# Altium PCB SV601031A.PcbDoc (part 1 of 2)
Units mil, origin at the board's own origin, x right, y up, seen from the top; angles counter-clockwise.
Board outline 4000 x 2000 mil, 6 copper layers (Top Layer, MidLayer1, MidLayer2, Mid-Layer 3, Mid-Layer 4, Bottom Layer), stack 60.8 mil thick; 81 components, 26 nets, 217 pads, 227 vias.
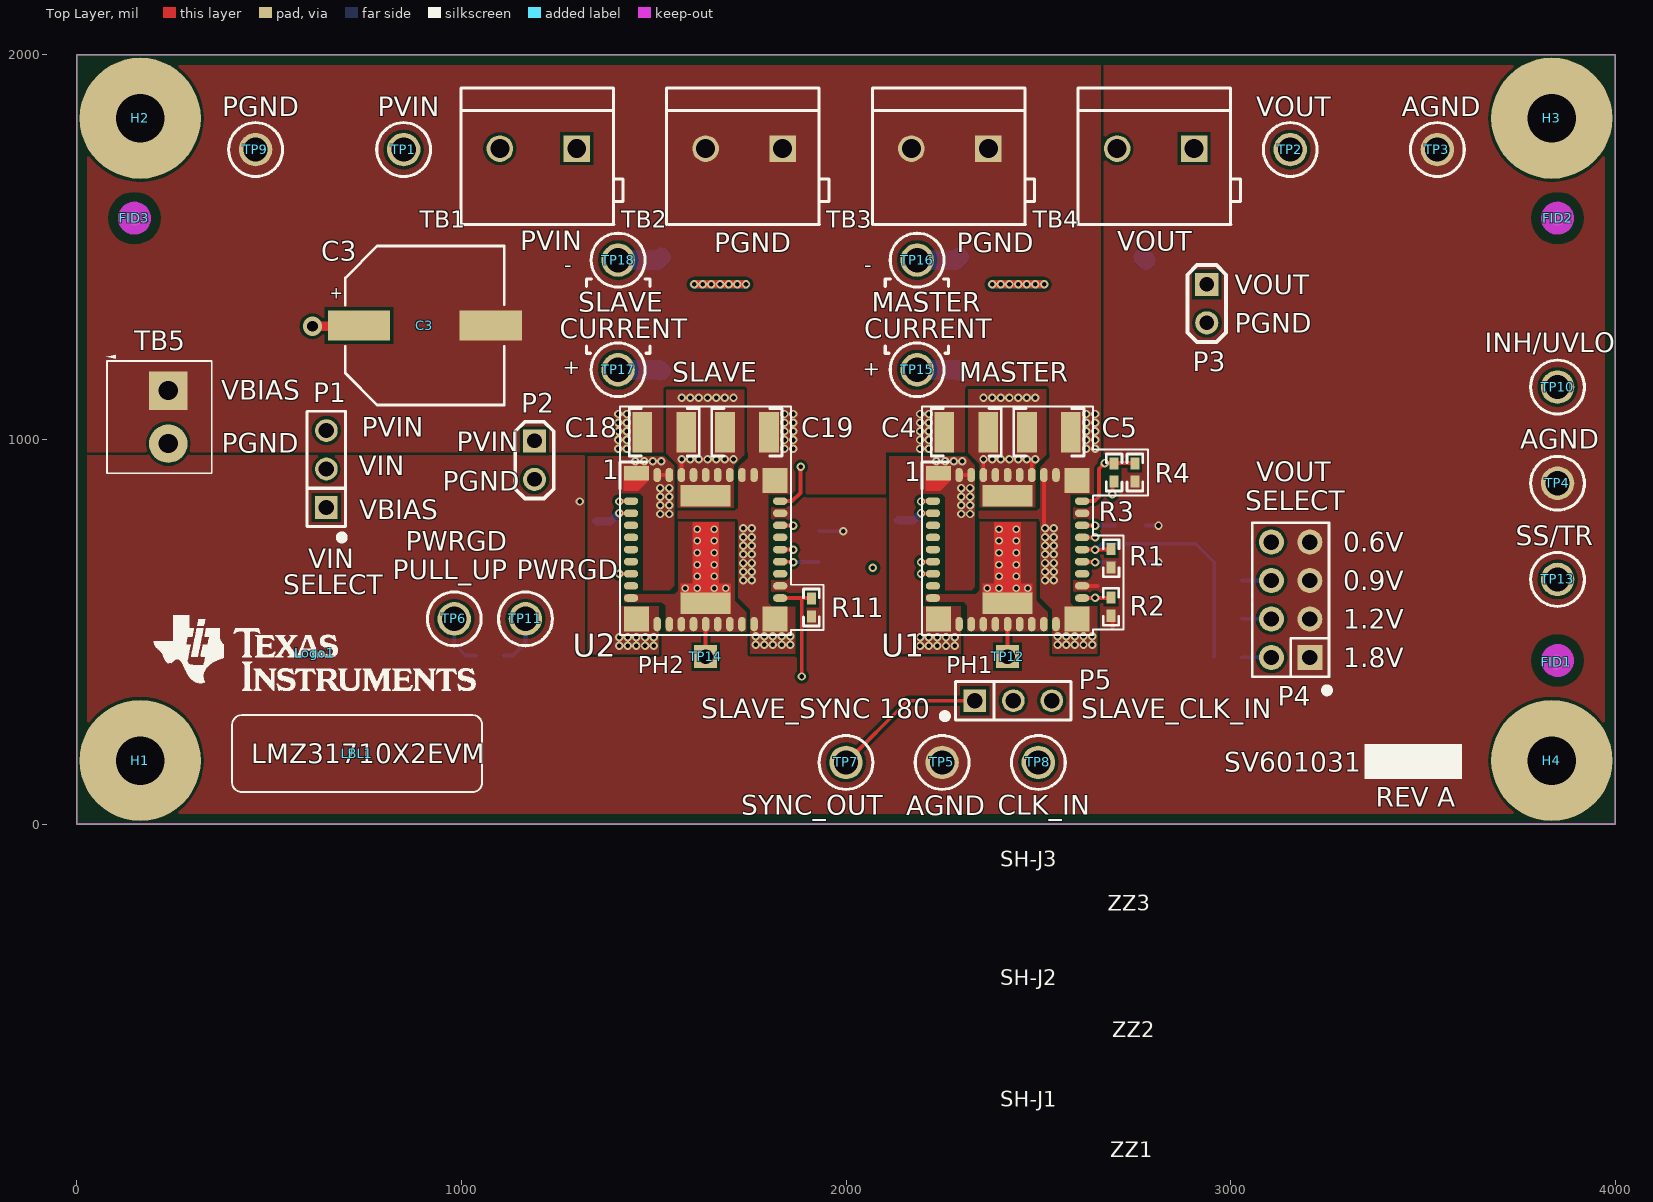
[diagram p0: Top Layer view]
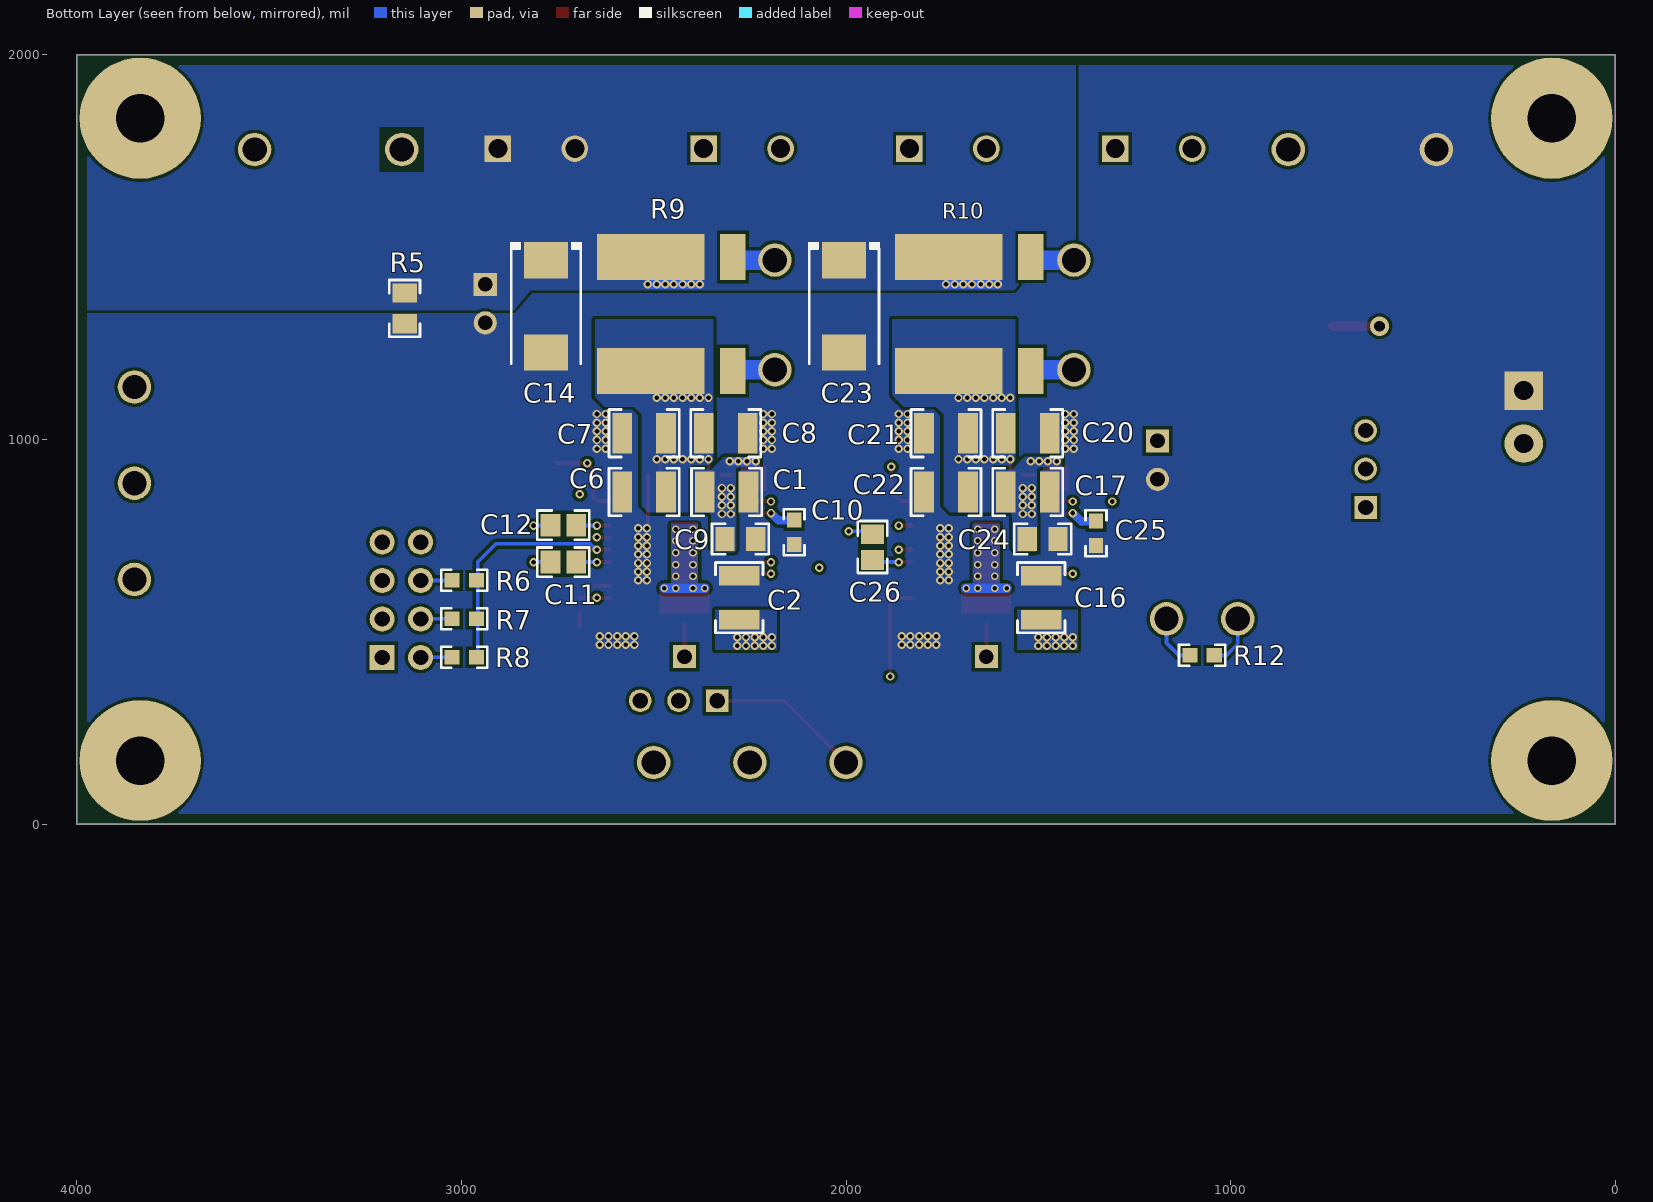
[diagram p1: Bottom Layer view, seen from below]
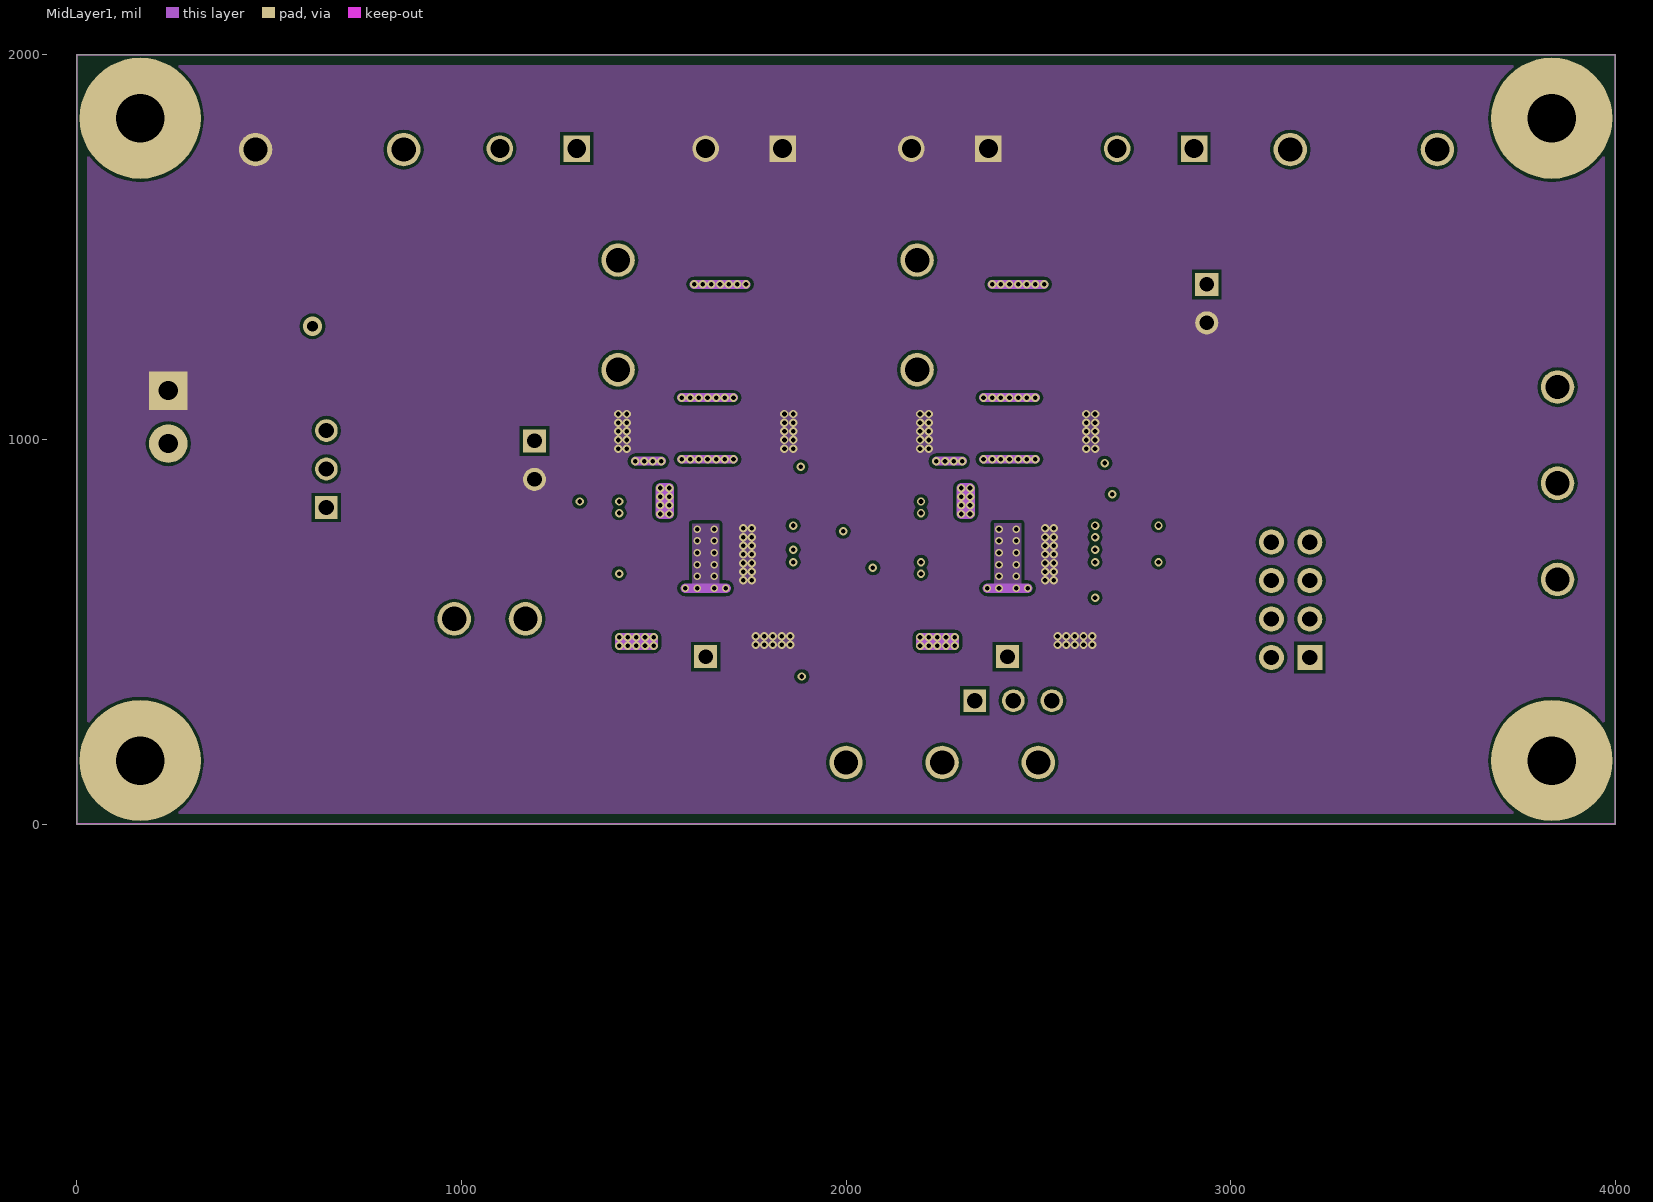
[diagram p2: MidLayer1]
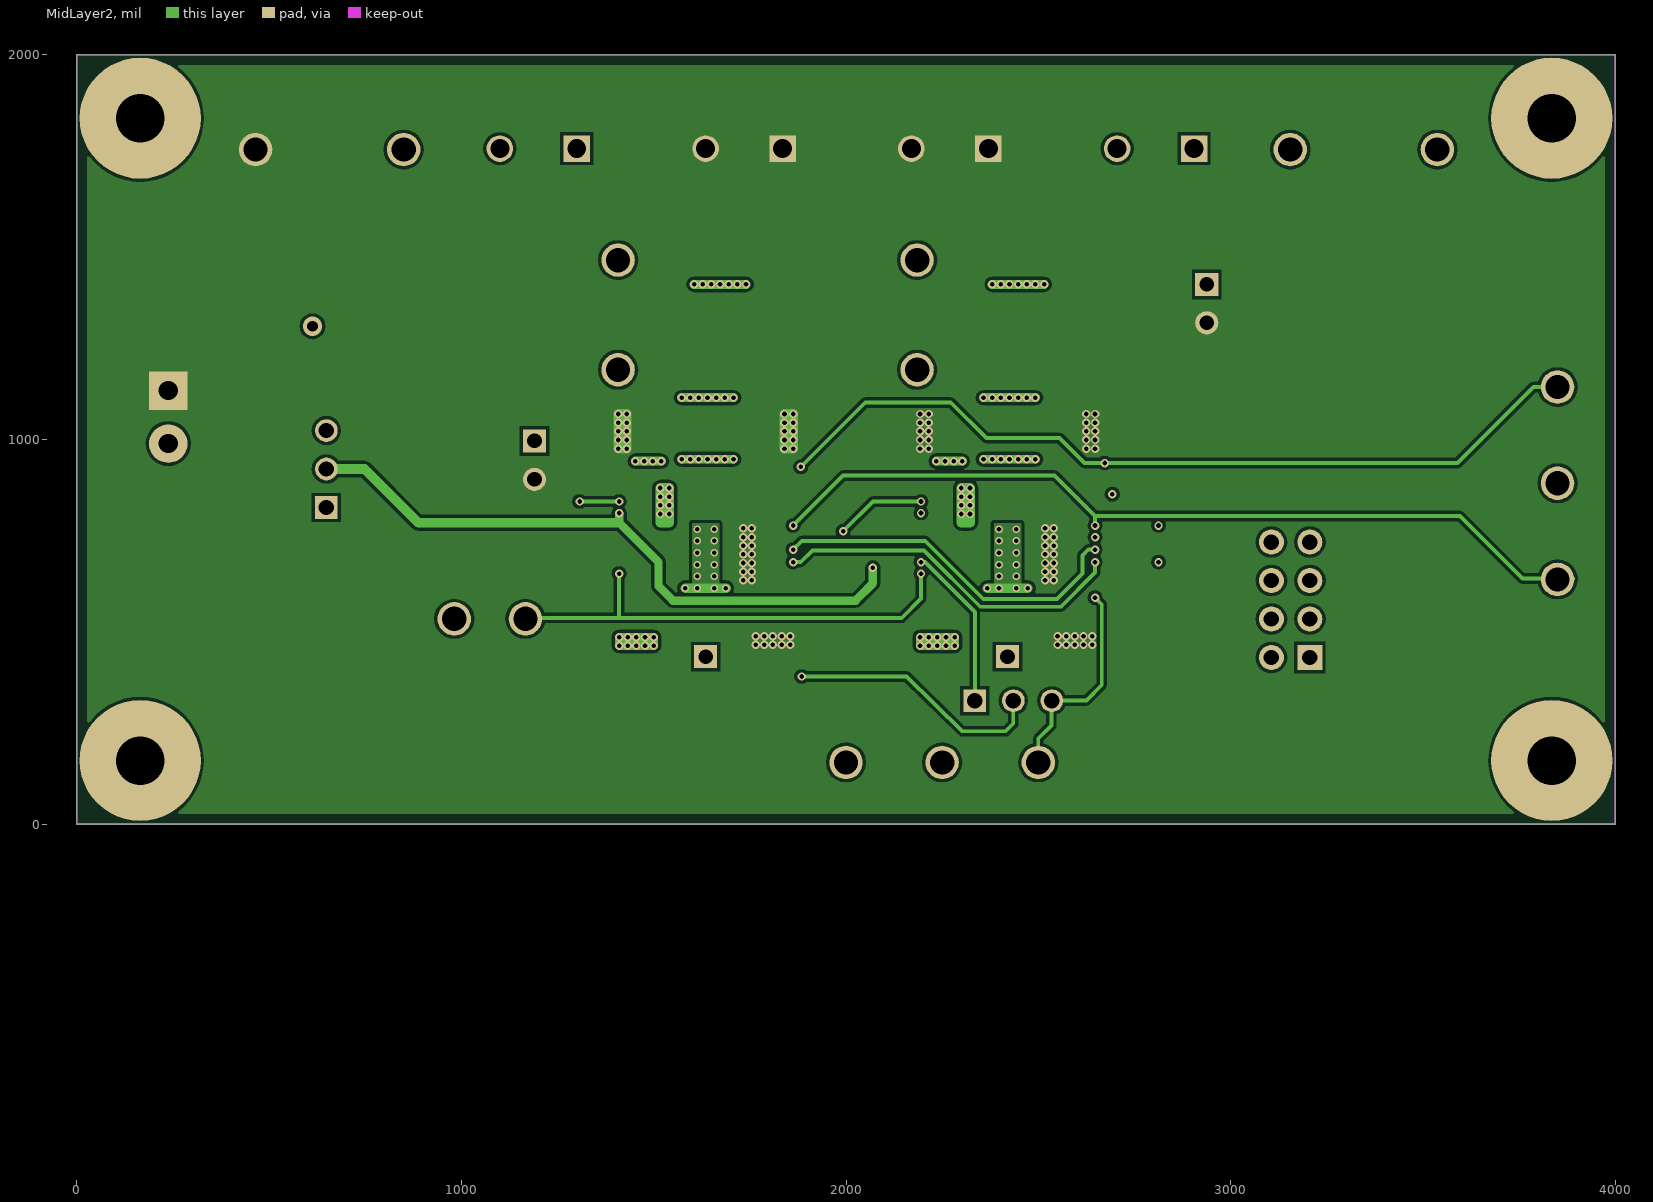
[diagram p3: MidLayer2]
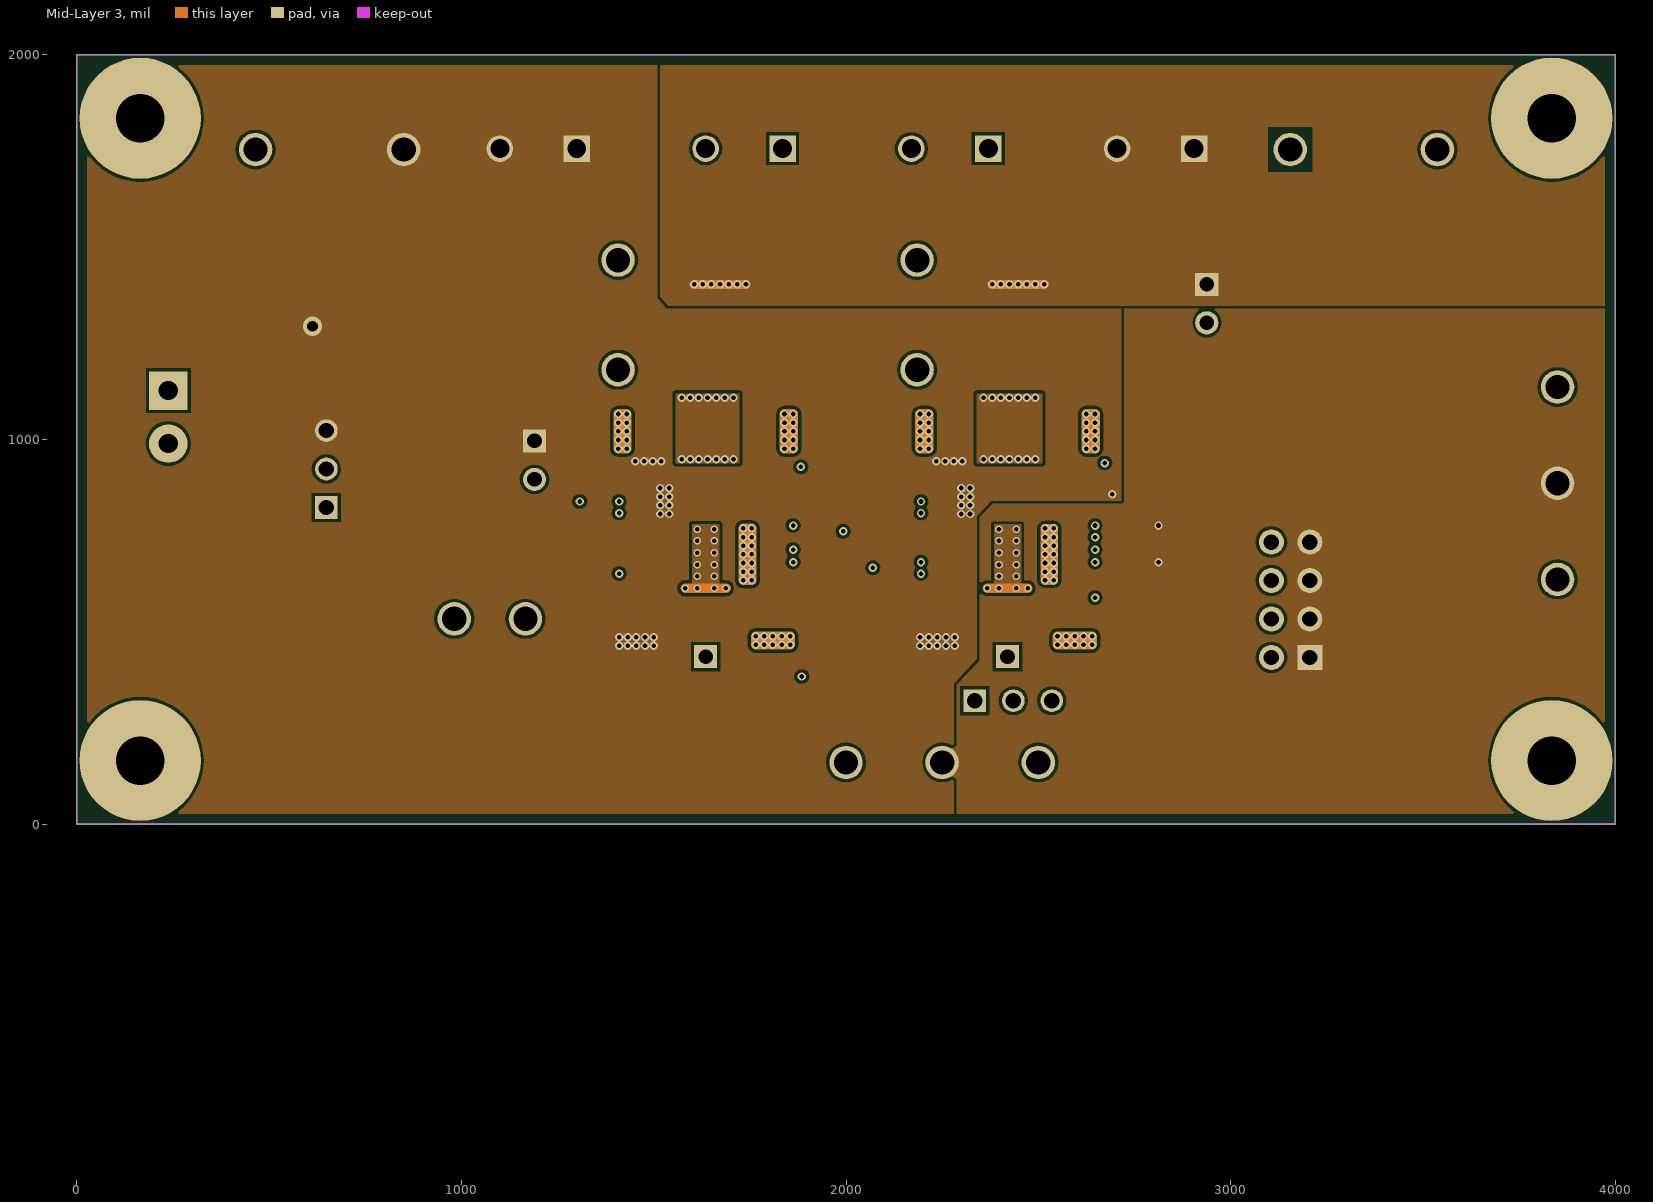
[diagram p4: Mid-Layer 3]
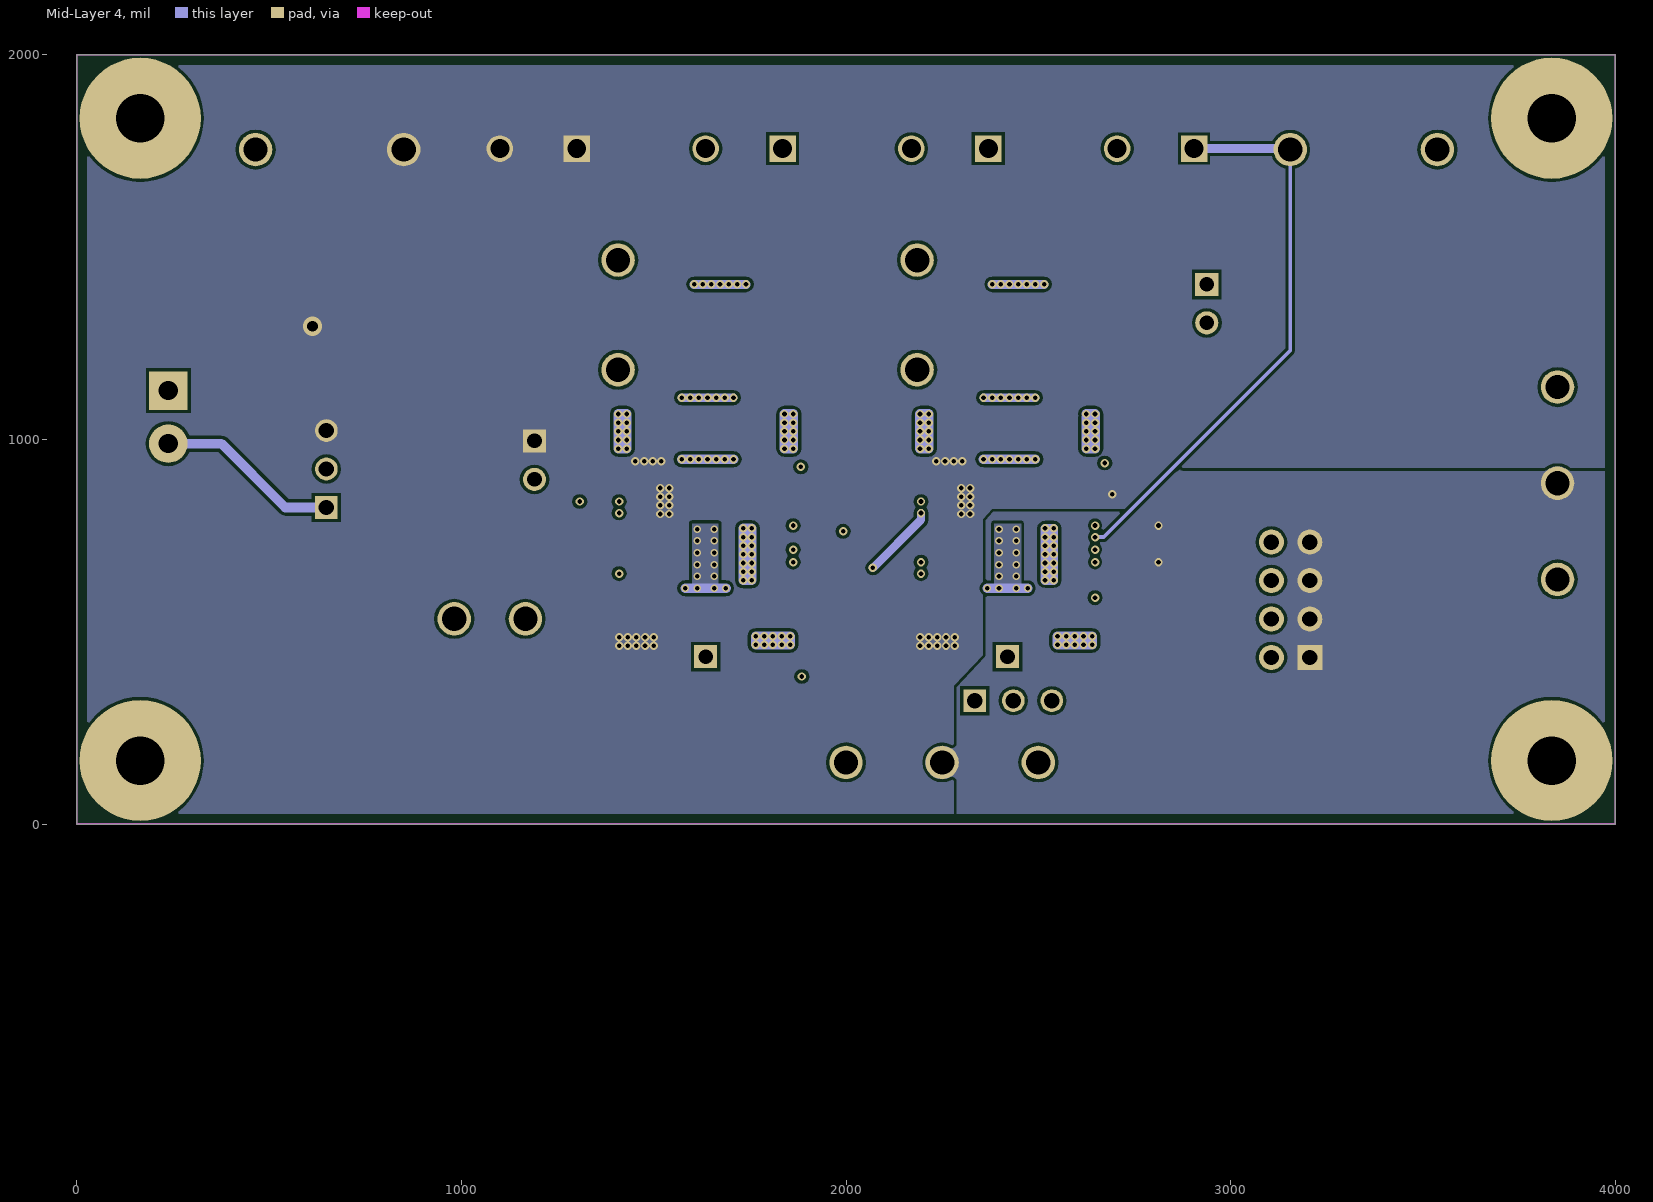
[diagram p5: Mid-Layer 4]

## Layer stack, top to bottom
Top Layer: signal copper 2.8
Dielectric: core 6, FR-4, Dk 4.8
MidLayer1: signal copper 2.8
Dielectric: prepreg 13, FR-4, Dk 4.8
MidLayer2: signal copper 2.8
Dielectric: core 6, FR-4, Dk 4.8
Mid-Layer 3: signal copper 2.8
Dielectric: prepreg 13, FR-4, Dk 4.8
Mid-Layer 4: signal copper 2.8
Dielectric: core 6, FR-4, Dk 4.8
Bottom Layer: signal copper 2.8

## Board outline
0,0 0,2000 4000,2000 4000,0

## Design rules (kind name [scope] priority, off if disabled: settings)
AcuteAngle [All] p1: minimum=4.50000000000000E+0001 checktracksonly=FALSE
AssemblyTestPointUsage [All] p1: valid=2
AssemblyTestpoint [All] p1: testpointundercomponent=TRUE minsize=20 maxsize=100 preferedsize=60 minholesize=0 maxholesize=40 preferedholesize=32 testpointgrid=1 usegrid=FALSE gridtolerance=0.01 allowsidetop=TRUE allowsidebottom=TRUE
Clearance Clearance_1 [IsVia vs IsVia] p1 off: gap=0
Clearance Clearance_BoardEdge_MountingHoles [OnCopper and InComponentClass('Mounting Holes') vs IsKeepOut] p2: gap=4
Clearance Clearance_BoardEdge_Poly [OnCopper and InPoly vs IsKeepOut] p3: gap=25
Clearance Clearance_BoardEdge [OnCopper and Not InComponentClass('Logo') and not InComponentClass('FiducialMark') and not InRegion(1000,500,4000,800) and Not IsKeepout vs IsKeepOut] p4: gap=75
Clearance Clearance_Poly [InPolygon] p5: gap=8
Clearance [All] p6: gap=8
ComponentClearance ComponentClearance_1 [InComponent('U2') vs InComponent('TP14')] p1: gap=5 collisioncheckmode=3 verticalgap=5 showdistances=FALSE
ComponentClearance ComponentClearance_U1-TP12 [InComponent('U1') vs InComponent('TP12')] p2: gap=5 collisioncheckmode=3 verticalgap=5 showdistances=FALSE
ComponentClearance ComponentClearance_Logo-TP6 [InComponent('Logo1') vs InComponent('TP6')] p3: gap=0 collisioncheckmode=3 verticalgap=0 showdistances=FALSE
ComponentClearance ComponentClearance_P5-TP12 [InComponent('P5') vs InComponent('TP12')] p4: gap=8 collisioncheckmode=3 verticalgap=20 showdistances=FALSE
ComponentClearance ComponentClearance_Logo [InComponentClass('Logo')] p5: gap=50 collisioncheckmode=3 verticalgap=10 showdistances=FALSE
ComponentClearance ComponentClearance_ScrewToNut [(HasFootprint('NY PMS 440 0025 PH')) vs (HasFootprint('Keystone_1902C'))] p6: gap=5 collisioncheckmode=3 verticalgap=10 showdistances=FALSE
ComponentClearance ComponentClearance_MountingHoles [InComponentClass('Mounting Holes')] p7: gap=50 collisioncheckmode=3 verticalgap=50 showdistances=FALSE
ComponentClearance ComponentClearance_SmallPassives [HasFootprint('0201*') or HasFootprint('0402*') or HasFootprint('0508') or HasFootprint('0603*') or HasFootprint('0612') or HasFootprint('0805*') or HasFootprint('0815*') or HasFootprint('0830*') or HasFootprint('1206*') or HasFootprint('1210*') or HasFootprint('1808*') or HasFootprint('1812*') or HasFootprint('1825*') or HasFootprint('2010*') or HasFootprint('2220*') or HasFootprint('2225*') or HasFootprint('2512*') or HasFootprint('2728*') or HasFootprint('3518*') vs HasFootprint('0201*') or HasFootprint('0402*') or HasFootprint('0508') or HasFootprint('0603*') or HasFootprint('0612') or HasFootprint('0805*') or HasFootprint('0815*') or HasFootprint('0830*') or HasFootprint('1206*') or HasFootprint('1210*') or HasFootprint('1808*') or HasFootprint('1812*') or HasFootprint('1825*') or HasFootprint('2010*') or HasFootprint('2220*') or HasFootprint('2225*') or HasFootprint('2512*') or HasFootprint('2728*') or HasFootprint('3518*')] p8: gap=20 collisioncheckmode=3 verticalgap=10 showdistances=FALSE
ComponentClearance ComponentClearance_THtoSMT [IsThruComponent vs IsSMTComponent] p9: gap=30 collisioncheckmode=3 verticalgap=30 showdistances=FALSE
ComponentClearance ComponentClearance_THtoTH_2 [IsThruComponent vs IsThruComponent] p10: gap=30 collisioncheckmode=3 verticalgap=20 showdistances=FALSE
ComponentClearance [All] p11: gap=15 collisioncheckmode=3 verticalgap=10 showdistances=FALSE
DiffPairsRouting [All] p1: maxlimit=100 minlimit=10 mostfreqgap=10 maxuncoupledlength=1000
FabricationTestPointUsage TestPointUsage [All] p1: valid=2 allowmultiple=FALSE
FabricationTestpoint Testpoint [All] p1: side=3 testpointundercomponent=TRUE minsize=20 maxsize=100 preferedsize=60 minholesize=0 maxholesize=40 preferedholesize=32 testpointgrid=1 allowsidetop=TRUE allowsidebottom=TRUE usegrid=FALSE gridtolerance=0.01
FanoutControl Fanout_LCC [IsLCC] p1: bgadir=Out bgaviamode=Centered fanoutstyle=Auto fanoutdirection=Alternating viagrid=1 // Fanout_LCC (Default Rule)
FanoutControl Fanout_BGA [IsBGA] p2: bgadir=Out bgaviamode=Centered fanoutstyle=Auto fanoutdirection=Alternating viagrid=1 // Fanout_BGA (Default Rule)
FanoutControl Fanout_Default [All] p4: bgadir=Out bgaviamode=Centered fanoutstyle=Auto fanoutdirection=Alternating viagrid=1 // Fanout_Default (Default Rule)
FanoutControl Fanout_Small [(CompPinCount < 5)] p5: bgadir=Out bgaviamode=Centered fanoutstyle=Auto fanoutdirection=OutThenIn viagrid=1 // Fanout_Small (Default Rule)
HoleSize [All] p1: absolutevalues=TRUE maxlimit=251 minlimit=8 maxpercent=80.000 minpercent=20.000
MinimumAnnularRing MinimumAnnularRing_2 [InNet('PH')] p1: minimumring=3
MinimumAnnularRing MinimumAnnularRing_1 [InNet('PH2')] p2: minimumring=3
MinimumAnnularRing [All] p3: minimumring=5
MinimumSolderMaskSliver MinimumSolderMaskSliver_6 [InComponent('U2') vs InNet('PRE_VOUT2')] p1: minsoldermaskwidth=1
MinimumSolderMaskSliver MinimumSolderMaskSliver_5 [InComponent('U1') vs InNet('PRE_VOUT')] p2: minsoldermaskwidth=1
MinimumSolderMaskSliver MinimumSolderMaskSliver_4 [InComponent('C24') vs IsVia] p3: minsoldermaskwidth=1
MinimumSolderMaskSliver MinimumSolderMaskSliver_3 [InComponent('R10') vs IsVia] p4: minsoldermaskwidth=1
MinimumSolderMaskSliver MinimumSolderMaskSliver_1 [InComponent('R9') vs IsVia] p5: minsoldermaskwidth=1
MinimumSolderMaskSliver MinimumSolderMaskSliver_2 [InComponent('C9') vs IsVia] p6: minsoldermaskwidth=1
MinimumSolderMaskSliver [All] p7: minsoldermaskwidth=4
MinimumSolderMaskSliver MinimumSolderMaskSliver_Logo [InComponentClass('Logo') vs InComponentClass('Logo')] p8: minsoldermaskwidth=0.7
PlaneClearance [All] p1: clearance=8
PlaneConnect [All] p1: planeconnectstyle=Relief reliefexpansion=10 reliefentries=4 reliefconductorwidth=10 reliefairgap=10
PolygonConnect PolygonConnect_53 [All vs IsNamedPolygon('Bottom-PGND')] p1: connectstyle=Direct reliefconductorwidth=10 reliefentries=4 polygonreliefangle="90 Angle" airgapwidth=10
PolygonConnect PolygonConnect_52 [All vs IsNamedPolygon('Bottom-VOUT')] p2: connectstyle=Direct reliefconductorwidth=10 reliefentries=4 polygonreliefangle="90 Angle" airgapwidth=10
PolygonConnect PolygonConnect_51 [All vs IsNamedPolygon('Bottom-PH')] p3: connectstyle=Direct reliefconductorwidth=10 reliefentries=4 polygonreliefangle="90 Angle" airgapwidth=10
PolygonConnect PolygonConnect_50 [All vs IsNamedPolygon('Bottom-VOUT')] p4: connectstyle=Direct reliefconductorwidth=10 reliefentries=4 polygonreliefangle="90 Angle" airgapwidth=10
PolygonConnect PolygonConnect_49 [All vs IsNamedPolygon('Bottom-PGND')] p5: connectstyle=Direct reliefconductorwidth=10 reliefentries=4 polygonreliefangle="90 Angle" airgapwidth=10
PolygonConnect PolygonConnect_48 [All vs IsNamedPolygon('Bottom-PVIN 1')] p6: connectstyle=Direct reliefconductorwidth=10 reliefentries=4 polygonreliefangle="90 Angle" airgapwidth=10
PolygonConnect PolygonConnect_47 [All vs IsNamedPolygon('Bottom-$$$2')] p7: connectstyle=Direct reliefconductorwidth=10 reliefentries=4 polygonreliefangle="90 Angle" airgapwidth=10
PolygonConnect PolygonConnect_46 [All vs IsNamedPolygon('Bottom-PVIN 3')] p8: connectstyle=Direct reliefconductorwidth=10 reliefentries=4 polygonreliefangle="90 Angle" airgapwidth=10
PolygonConnect PolygonConnect_45 [All vs IsNamedPolygon('Bottom-PVIN 2')] p9: connectstyle=Direct reliefconductorwidth=10 reliefentries=4 polygonreliefangle="90 Angle" airgapwidth=10
PolygonConnect PolygonConnect_44 [All vs IsNamedPolygon('Bottom-PH2')] p10: connectstyle=Direct reliefconductorwidth=10 reliefentries=4 polygonreliefangle="90 Angle" airgapwidth=10
PolygonConnect PolygonConnect_43 [All vs IsNamedPolygon('Bottom-$$$1')] p11: connectstyle=Direct reliefconductorwidth=10 reliefentries=4 polygonreliefangle="90 Angle" airgapwidth=10
PolygonConnect PolygonConnect_42 [All vs IsNamedPolygon('Bottom-PVIN')] p12: connectstyle=Direct reliefconductorwidth=10 reliefentries=4 polygonreliefangle="90 Angle" airgapwidth=10
PolygonConnect PolygonConnect_41 [All vs IsNamedPolygon('Bottom-$$$11361')] p13: connectstyle=Direct reliefconductorwidth=10 reliefentries=4 polygonreliefangle="90 Angle" airgapwidth=10
PolygonConnect PolygonConnect_40 [All vs IsNamedPolygon('Bottom-PGND')] p14: connectstyle=Direct reliefconductorwidth=10 reliefentries=4 polygonreliefangle="90 Angle" airgapwidth=10
PolygonConnect PolygonConnect_39 [All vs IsNamedPolygon('Bottom-VOUT')] p15: connectstyle=Direct reliefconductorwidth=10 reliefentries=4 polygonreliefangle="90 Angle" airgapwidth=10
PolygonConnect PolygonConnect_38 [All vs IsNamedPolygon('Layer 5-AGND')] p16: connectstyle=Direct reliefconductorwidth=10 reliefentries=4 polygonreliefangle="90 Angle" airgapwidth=10
PolygonConnect PolygonConnect_37 [All vs IsNamedPolygon('Layer 5-PVIN')] p17: connectstyle=Direct reliefconductorwidth=10 reliefentries=4 polygonreliefangle="90 Angle" airgapwidth=10
PolygonConnect PolygonConnect_36 [All vs IsNamedPolygon('Layer 5-PH2')] p18: connectstyle=Direct reliefconductorwidth=10 reliefentries=4 polygonreliefangle="90 Angle" airgapwidth=10
PolygonConnect PolygonConnect_35 [All vs IsNamedPolygon('Layer 5-PH')] p19: connectstyle=Direct reliefconductorwidth=10 reliefentries=4 polygonreliefangle="90 Angle" airgapwidth=10
PolygonConnect PolygonConnect_34 [All vs IsNamedPolygon('Layer 4-AGND')] p20: connectstyle=Direct reliefconductorwidth=10 reliefentries=4 polygonreliefangle="90 Angle" airgapwidth=10
PolygonConnect PolygonConnect_33 [All vs IsNamedPolygon('Layer 4-$$$')] p21: connectstyle=Direct reliefconductorwidth=10 reliefentries=4 polygonreliefangle="90 Angle" airgapwidth=10
PolygonConnect PolygonConnect_32 [All vs IsNamedPolygon('Layer 4-$$$2')] p22: connectstyle=Direct reliefconductorwidth=10 reliefentries=4 polygonreliefangle="90 Angle" airgapwidth=10
PolygonConnect PolygonConnect_31 [All vs IsNamedPolygon('Layer 4-PVIN')] p23: connectstyle=Direct reliefconductorwidth=10 reliefentries=4 polygonreliefangle="90 Angle" airgapwidth=10
PolygonConnect PolygonConnect_30 [All vs IsNamedPolygon('Layer 4-VOUT')] p24: connectstyle=Direct reliefconductorwidth=10 reliefentries=4 polygonreliefangle="90 Angle" airgapwidth=10
PolygonConnect PolygonConnect_29 [All vs IsNamedPolygon('Layer 4-PH')] p25: connectstyle=Direct reliefconductorwidth=10 reliefentries=4 polygonreliefangle="90 Angle" airgapwidth=10
PolygonConnect PolygonConnect_28 [All vs IsNamedPolygon('Layer 4-PH2')] p26: connectstyle=Direct reliefconductorwidth=10 reliefentries=4 polygonreliefangle="90 Angle" airgapwidth=10
PolygonConnect PolygonConnect_27 [All vs IsNamedPolygon('Layer 3-PGND')] p27: connectstyle=Direct reliefconductorwidth=10 reliefentries=4 polygonreliefangle="90 Angle" airgapwidth=10
PolygonConnect PolygonConnect_26 [All vs IsNamedPolygon('Layer 3-PH2')] p28: connectstyle=Direct reliefconductorwidth=10 reliefentries=4 polygonreliefangle="90 Angle" airgapwidth=10
PolygonConnect PolygonConnect_25 [All vs IsNamedPolygon('Layer 3-PH')] p29: connectstyle=Direct reliefconductorwidth=10 reliefentries=4 polygonreliefangle="90 Angle" airgapwidth=10
PolygonConnect PolygonConnect_24 [All vs IsNamedPolygon('Layer 2-PGND')] p30: connectstyle=Direct reliefconductorwidth=10 reliefentries=4 polygonreliefangle="90 Angle" airgapwidth=10
PolygonConnect PolygonConnect_23 [InNet('PGND') vs IsNamedPolygon('Layer 2-PH')] p31: connectstyle=Direct reliefconductorwidth=10 reliefentries=4 polygonreliefangle="90 Angle" airgapwidth=10
PolygonConnect PolygonConnect_22 [All vs IsNamedPolygon('Layer 2-PH2')] p32: connectstyle=Direct reliefconductorwidth=10 reliefentries=2 polygonreliefangle="90 Angle" airgapwidth=10
PolygonConnect PolygonConnect_21 [All vs IsNamedPolygon('Layer 2-PH')] p33: connectstyle=Direct reliefconductorwidth=10 reliefentries=2 polygonreliefangle="90 Angle" airgapwidth=10
PolygonConnect PolygonConnect_20 [All vs IsNamedPolygon('Layer 2-PH2')] p34: connectstyle=Direct reliefconductorwidth=10 reliefentries=4 polygonreliefangle="90 Angle" airgapwidth=10
PolygonConnect PolygonConnect_19 [All vs IsNamedPolygon('Layer 2-PH')] p35: connectstyle=Direct reliefconductorwidth=10 reliefentries=4 polygonreliefangle="90 Angle" airgapwidth=10
PolygonConnect PolygonConnect_18 [All vs IsNamedPolygon('Layer 2-PH2')] p36: connectstyle=Direct reliefconductorwidth=10 reliefentries=4 polygonreliefangle="90 Angle" airgapwidth=10
PolygonConnect PolygonConnect_17 [All vs IsNamedPolygon('Layer 2-PH')] p37: connectstyle=Direct reliefconductorwidth=10 reliefentries=4 polygonreliefangle="90 Angle" airgapwidth=10
PolygonConnect PolygonConnect_16 [All vs IsNamedPolygon('Layer 2-PH')] p38: connectstyle=Direct reliefconductorwidth=10 reliefentries=4 polygonreliefangle="90 Angle" airgapwidth=10
PolygonConnect PolygonConnect_15 [All vs IsNamedPolygon('Top-$$$')] p39: connectstyle=Direct reliefconductorwidth=10 reliefentries=4 polygonreliefangle="90 Angle" airgapwidth=10
PolygonConnect PolygonConnect_14 [All vs IsNamedPolygon('Top-AGND')] p40: connectstyle=Direct reliefconductorwidth=10 reliefentries=4 polygonreliefangle="90 Angle" airgapwidth=10
PolygonConnect PolygonConnect_13 [All vs IsNamedPolygon('Top-PGND 1')] p41: connectstyle=Direct reliefconductorwidth=10 reliefentries=4 polygonreliefangle="90 Angle" airgapwidth=10
PolygonConnect PolygonConnect_12 [All vs IsNamedPolygon('Top-$$$')] p42: connectstyle=Direct reliefconductorwidth=10 reliefentries=4 polygonreliefangle="90 Angle" airgapwidth=10
PolygonConnect PolygonConnect_11 [All vs IsNamedPolygon('Top-$$$')] p43: connectstyle=Direct reliefconductorwidth=10 reliefentries=4 polygonreliefangle="90 Angle" airgapwidth=10
PolygonConnect PolygonConnect_10 [All vs IsNamedPolygon('Top-$$$2')] p44: connectstyle=Direct reliefconductorwidth=10 reliefentries=4 polygonreliefangle="90 Angle" airgapwidth=10
PolygonConnect PolygonConnect_9 [All vs IsNamedPolygon('Top-PGND 2')] p45: connectstyle=Direct reliefconductorwidth=10 reliefentries=4 polygonreliefangle="90 Angle" airgapwidth=10
PolygonConnect PolygonConnect_8 [All vs IsNamedPolygon('Top-PVIN 2')] p46: connectstyle=Direct reliefconductorwidth=10 reliefentries=4 polygonreliefangle="90 Angle" airgapwidth=10
PolygonConnect PolygonConnect_7 [All vs IsNamedPolygon('Top-PVIN 1')] p47: connectstyle=Direct reliefconductorwidth=10 reliefentries=4 polygonreliefangle="90 Angle" airgapwidth=10
PolygonConnect PolygonConnect_6 [All vs IsNamedPolygon('Top-PH2')] p48: connectstyle=Direct reliefconductorwidth=10 reliefentries=4 polygonreliefangle="90 Angle" airgapwidth=10
PolygonConnect PolygonConnect_5 [All vs IsNamedPolygon('Top-PVIN 1')] p49: connectstyle=Direct reliefconductorwidth=10 reliefentries=4 polygonreliefangle="90 Angle" airgapwidth=10
PolygonConnect PolygonConnect_4 [All vs IsNamedPolygon('Top-PH2')] p50: connectstyle=Direct reliefconductorwidth=10 reliefentries=4 polygonreliefangle="90 Angle" airgapwidth=10
PolygonConnect PolygonConnect_3 [All vs IsNamedPolygon('Top-PH2')] p51: connectstyle=Direct reliefconductorwidth=10 reliefentries=4 polygonreliefangle="90 Angle" airgapwidth=10
PolygonConnect PolygonConnect_2 [All vs IsNamedPolygon('Top-PGND')] p52: connectstyle=Direct reliefconductorwidth=10 reliefentries=4 polygonreliefangle="90 Angle" airgapwidth=10
PolygonConnect PolygonConnect_1 [All vs IsNamedPolygon('Top-PH')] p53: connectstyle=Direct reliefconductorwidth=10 reliefentries=4 polygonreliefangle="90 Angle" airgapwidth=10
PolygonConnect [All] p54: connectstyle=Relief reliefconductorwidth=10 reliefentries=4 polygonreliefangle="90 Angle" airgapwidth=10
RoutingVias [All] p1: holewidth=12 width=24 viastyle="Through Hole" minholewidth=8 minwidth=19 maxholewidth=40 maxwidth=65
SMDToCorner [All] p1: distance=30000
SilkToSilkClearance [All] p1: silktosilkclearance=1
SilkscreenOverComponentPads [All] p1: minsilkscreentomaskgap=5
SolderMaskExpansion [All] p1: expansion=3
Width [All] p1: maxlimit=100 minlimit=6 preferedwidth=10 checkconnectedcopper=TRUE
12 further rules are at their usual default settings.

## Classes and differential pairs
component class Shunt: SH-J1 SH-J2 SH-J3
component class "Mounting Holes": H1 H2 H3 H4
component class Label: LBL1
component class AssemblyNote: ZZ2 ZZ3
component class FiducialMark: FID1 FID2 FID3
component class Logo: Logo1

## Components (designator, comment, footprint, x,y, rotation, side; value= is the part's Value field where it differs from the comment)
C1 "12103D226MAT2A" 1210 2310.5,863.5 r180 bottom
C2 "12103D226MAT2A" 1210 2277.5,588.5 r90 bottom
C3 "EEE-FC1E221P" SM_RADIAL_G 905,1296 r0 top
C4 "GRM32EC80J107ME20L" 1210 2527.5,1018.5 r0 top
C5 "GRM32EC80J107ME20L" 1210 2312.5,1018.5 r180 top
C6 "GRM32EC80J107ME20L" 1210 2525,863.5 r0 bottom
C7 "GRM32EC80J107ME20L" 1210 2312.5,1016 r180 bottom
C8 "GRM32EC80J107ME20L" 1210 2525,1016 r0 bottom
C9 "C0805C104K3RACTU" 0805_HV 2274.5,741 r180 bottom
C10 "GRM188R60J475KE19D" 0603 2135,758.5 r270 bottom
C11 "GRM2165C2A101JA01D" 0805 2735,681 r0 bottom
C12 "C0805C332K5RACTU" 0805 2735,777 r0 bottom
C14 "10TPB220M" TPB_D4 2780,1346 r270 bottom
C16 "12103D226MAT2A" 1210 1492.5,588.5 r90 bottom
C17 "12103D226MAT2A" 1210 1527.5,863.5 r180 bottom
C18 "GRM32EC80J107ME20L" 1210 1742.5,1018.5 r0 top
C19 "GRM32EC80J107ME20L" 1210 1527.5,1018.5 r180 top
C20 "GRM32EC80J107ME20L" 1210 1740,1016 r0 bottom
C21 "GRM32EC80J107ME20L" 1210 1527.5,1016 r180 bottom
C22 "GRM32EC80J107ME20L" 1210 1740,863.5 r0 bottom
C23 "10TPB220M" TPB_D4 2005,1346 r270 bottom
C24 "C0805C104K3RACTU" 0805_HV 1488.5,741 r180 bottom
C25 "GRM188R60J475KE19D" 0603 1350,756 r270 bottom
C26 "GRM2165C2A101JA01D" 0805 1931,720 r90 bottom
FID1 "Fiducial" Fiducial10-20#1 3850,425 r0 top
FID2 "Fiducial" Fiducial10-20#2 3850,1575 r0 top
FID3 "Fiducial" Fiducial10-20#2 150,1575 r0 top
H1 "NY PMS 440 0025 PH" "NY PMS 440 0025 PH" 165,165 r90 top
H2 "NY PMS 440 0025 PH" "NY PMS 440 0025 PH" 165,1835 r90 top
H3 "NY PMS 440 0025 PH" "NY PMS 440 0025 PH" 3835,1835 r90 top
H4 "NY PMS 440 0025 PH" "NY PMS 440 0025 PH" 3835,165 r180 top
LBL1 "Size: 0.65\" x 0.20 \"" Label_650x200 729,183 r180 top
Logo1 "Texas Instruments" TI_Stacked_Overlay_Small 619,444 r0 top
P1 "PEC03SAAN" CONN_PEC03SAAN 649,923 r90 top
P2 "310-93-102-41-001000" HDR100_1X2 1190,996 r270 top
P3 "310-93-102-41-001000" HDR100_1X2 2938,1403 r270 top
P4 "PEC04DAAN" CONN_PEC04DAAN 3156,583 r90 top
P5 "PEC03SAAN" CONN_PEC03SAAN 2435,320.5 r0 top
R1 "CRCW04022K15FKED" 0402 2689.5,691 r90 top
R2 "CRCW0402487KFKED" 0402 2689,565 r90 top
R3 "CRCW040268K1FKED" 0402 2697,914 r270 top
R4 "CRCW040224K3FKED" 0402 2751,914 r90 top
R5 "ERJ-6GEYJ102V" 0805_HV 3147.5,1340.5 r270 bottom
R6 "CRCW06032K87FKEA" 0603 2992.5,633.5 r180 bottom
R7 "CRCW06031K43FKEA" 0603 2992.5,533.5 r180 bottom
R8 "CRCW0603715RFKEA" 0603 2992.5,433.5 r180 bottom
R9 "R-WSL3637" CSM-3637 2455,1326 r270 bottom
R10 "R-WSL3637" CSM-3637 1680,1326 r270 bottom
R11 "CRCW0402487KFKED" 0402 1910,563 r90 top
R12 "CRCW0603100KJNEA" 0603 1074,438.5 r180 bottom
SH-J1 "2SN-BK-G" 2SN-BK-G 2437,-844 r90 top
SH-J2 "2SN-BK-G" 2SN-BK-G 2437,-528 r90 top
SH-J3 "2SN-BK-G" 2SN-BK-G 2437,-219 r90 top
TB1 "ED120/2DS" CONN_ED120-2DS 1200,1756 r90 top
TB2 "ED120/2DS" CONN_ED120-2DS 1735,1756 r90 top
TB3 "ED120/2DS" CONN_ED120-2DS 2270,1756 r90 top
TB4 "ED120/2DS" CONN_ED120-2DS 2805,1756 r90 top
TB5 "ED555/2DS" TERM_BLK_ED555-2DS 238,1127 r270 top
TP1 "5010" Keystone5010 850,1753.5 r0 top
TP2 "5010" Keystone5010 3155,1753.5 r90 top
TP3 "5011" Keystone5011 3537.5,1753.5 r0 top
TP4 "5011" Keystone5011 3850,886 r0 top
TP5 "5011" Keystone5011 2250,160 r0 top
TP6 "5012" Keystone5012 981.5,533.5 r0 top
TP7 "5012" Keystone5012 2000,160 r0 top
TP8 "5012" Keystone5012 2500,160 r0 top
TP9 "5011" Keystone5011 465,1753.5 r180 top
TP10 "5012" Keystone5012 3850,1136 r90 top
TP11 "5012" Keystone5012 1166.5,533.5 r0 top
TP12 "Comment" TP-038 2420,435 r0 top
TP13 "5012" Keystone5012 3850,636 r90 top
TP14 "Comment" TP-038 1635,435 r0 top
TP15 "5012" Keystone5012 2185,1181 r0 top
TP16 "5012" Keystone5012 2185,1466 r0 top
TP17 "5012" Keystone5012 1407.5,1181 r0 top
TP18 "5012" Keystone5012 1407.5,1466 r90 top
U1 "LMZ31710RVQ" RVQ0042A 2420,713.5 r0 top locked
U2 "LMZ31710RVQ" RVQ0042A 1635,713.5 r0 top locked
ZZ1 "Place SH-J1 on P1 pins 2 and 3" AssemblyNote 2706,-898 r0 top
ZZ2 "Place SH-J2 on P4 pins 7 and 8" AssemblyNote 2706,-589 r0 top
ZZ3 "Place SH-J3 on P5 pins 1 and 2" AssemblyNote 2699,-276 r90 top

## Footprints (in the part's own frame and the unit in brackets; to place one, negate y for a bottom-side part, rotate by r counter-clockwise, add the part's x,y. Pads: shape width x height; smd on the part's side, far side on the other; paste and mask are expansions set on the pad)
2SN-BK-G [mil] "Samtec STEP model"
  round 1 on Mech3: 0(0,0)
  body extent -78,-39 79,39, height 188
0402 [mm] "0402 from SM-752 data"
  rect 0.8x0.6 smd: 1(-0.6,0) 2(0.6,0)
  silkscreen extent -1.22,-0.52 1.22,0.52, body extent -0.55,-0.3 0.55,0.3, height 0.6
0603 [mm] "0603 from SM-752 data"
  rect 1x0.95 smd: 1(-0.8,0) 2(0.8,0)
  silkscreen extent -1.52,-0.69 1.52,0.69, body extent -0.87,-0.47 0.87,0.47, height 0.85
0805 [mm] "0805 from SM-752 data"
  rect 1.3x1.5 smd: 1(-0.85,0) 2(0.85,0)
  silkscreen extent -1.72,-0.97 1.72,0.97, body extent -1.1,-0.72 1.1,0.72, height 1.1
0805_HV [mil] "0805 with 30mil clearance between pads"
  rect 50x63 smd: 1(-40,0) 2(40,0)
  silkscreen extent -74,-40 74,40, body extent -43,-29 43,29, height 43
1210 [mm] "1210 from SM-752 data"
  rect 1.3x2.7 smd: 1(-1.45,0) 2(1.45,0)
  silkscreen extent -2.32,-1.57 2.32,1.57, body extent -1.7,-1.35 1.7,1.35, height 1.35
AssemblyNote [mil] "Assembly Note"
CONN_ED120-2DS [mm] "ONSHORE"
  rect 1.75x1.75 hole 1.25: 1(0,-2.54)
  round 1.75 hole 1.25: 2(0,2.54)
  silkscreen extent -5,-5.6 4,5.12, body extent -5,-5.6 4.15,5.12, height 13.1
CONN_PEC03SAAN [mm] "SULLINS"
  rect 1.5x1.5 hole 1.016: 1(-2.54,0)
  round 1.5 hole 1.016: 2(0,0) 3(2.54,0)
  silkscreen extent -4.72,-1.27 3.81,1.27, body extent -3.84,-1.3 3.84,1.3, height 8.38
CONN_PEC04DAAN [mm] "SULLINS"
  rect 1.65x1.65 hole 1.016 mask+0: 1(-3.81,-1.27)
  round 1.65 hole 1.016 mask+0: 2(-3.81,1.27) 3(-1.27,-1.27) 4(-1.27,1.27) 5(1.27,-1.27) 6(1.27,1.27) 7(3.81,-1.27) 8(3.81,1.27)
  silkscreen extent -6.18,-2.6 5.08,2.54, body extent -5.08,-2.54 5.08,2.54, height 8.38
CSM-3637 [mil]
  rect 120x66 smd: 1(-148.5,160.6) 3(148.5,160.6)
  rect 120x280 smd: 2(-148.5,-52.5) 4(148.5,-52.5)
Fiducial10-20#1 [mil]
  round 39.37 smd paste-19.68 mask+19.68: 1(-3,-4)
  Top Layer keep-out circle w46.37: c0,0 r19.68
Fiducial10-20#2 [mil]
  round 39.37 smd paste-19.68 mask+19.68: 1(0,0)
  Top Layer keep-out circle w46.37: c0,0 r19.68
HDR100_1X2 [mil]
  rect 60x60 hole 38: 1(0,0)
  round 60 hole 38: 2(100,0)
  silkscreen extent -50,-50 150,50
Keystone5010 [mil] "Keystone Multipurpose loops"
  round 87 hole 63: 1(0,0)
  silkscreen extent -70,-70 70,70, body extent -63,-63 63,62, height 319
Keystone5011 [mil] "Keystone Multipurpose loops"
  round 87 hole 63: 1(0,0)
  silkscreen extent -70,-70 70,70, body extent -63,-63 63,62, height 319
Keystone5012 [mil] "Keystone Multipurpose loops"
  round 87 hole 63: 1(0,0)
  silkscreen extent -70,-70 70,70, body extent -63,-63 63,62, height 319
Label_650x200 [mil] "Thermal Transfer Label"
  round 1 on Mech13: 0(0,0)
  silkscreen extent -325,-100 325,100, body extent -326,-101 326,101, height 1
"NY PMS 440 0025 PH" [mm] "4-40 nylon screw and mounting hole"
  round 8 hole 3.2: 1(0,0)
  body extent -3.3,-3.3 3.3,3.3, height 2.69
RVQ0042A [mm]
  rect 1.65x0.95 smd paste-0.5: 1(-4.575,5.05)
  oval 0.95x0.5 smd paste-0.025: 2(-4.925,3.2) 3(-4.925,2.4) 4(-4.925,1.6) 5(-4.925,0.8) 6(-4.925,0) 7(-4.925,-0.8) 8(-4.925,-1.6) 9(-4.925,-2.4) 10(-4.925,-3.2) 22(4.925,-3.2) 23(4.925,-2.4) 24(4.925,-1.6) 25(4.925,-0.8) 26(4.925,0) 27(4.925,0.8) 28(4.925,1.6) 29(4.925,2.4) 30(4.925,3.2)
  rect 1.65x1.65 smd paste-0.225: 11(-4.575,-4.575) 21(4.575,-4.575) 31(4.575,4.575)
  oval 0.5x0.95 smd paste-0.025: 12(-3.2,-4.925) 13(-2.4,-4.925) 14(-1.6,-4.925) 15(-0.8,-4.925) 16(0,-4.925) 17(0.8,-4.925) 18(1.6,-4.925) 19(2.4,-4.925) 20(3.2,-4.925) 32(3.2,4.925) 33(2.4,4.925) 34(1.6,4.925) 35(0.8,4.925) 36(0,4.925) 37(-0.8,4.925) 38(-1.6,4.925) 39(-2.4,4.925) 40(-3.2,4.925)
  rect 3.29x1.4 smd paste-1: 41(0,3.55)
  rect 3.29x1.4 smd paste-1 mask+0: 42(0,-3.55)
  Top Layer region: -5.4,5.525 -3.75,5.525 -3.75,4.575 -4.45,3.875 -5.4,3.875
  Top Layer region: -1.645,-4.25 -1.645,-2.25 -0.863,-2.25 -0.863,1.8 0.863,1.8 0.863,-2.25 1.645,-2.25 1.645,-4.25
  silkscreen extent -5.65,4 -3.9,5.77, body extent -5.07,-5.07 5.07,5.07, height 4.41
SM_RADIAL_G [mm] "10 x 10.2mm:  Panasonic G"
  rect 4.1x2 smd: 1(-4.35,0) 2(4.35,0)
  silkscreen extent -5.25,-5.25 5.25,5.25, body extent -5.26,-5.26 5.26,5.26, height 10.5
TERM_BLK_ED555-2DS [mil]
  rect 100x100 hole 50: 1(0,0)
  round 100 hole 50: 2(138,0)
  silkscreen extent -93,-161 215,113, body extent -69,-150 207,106, height 323
TI_Stacked_Overlay_Small [mil]
  silkscreen extent -418,-98 418,98
TP-038 [mil]
  rect 60x60 hole 38: 1(0,0)
TPB_D4 [mm] "Panasonic recommended land pattern for size code D4"
  rect 2.4x2.9 smd: 1(-3.05,0) 2(3.05,0)
  silkscreen extent -4.25,-2.39 3.8,2.39, body extent -3.8,-2.3 3.8,2.3, height 4.01

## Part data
C1 C2 C16 C17: "CAP, CERM, 22uF, 25V, +/-20%, X5R, 1210"
C3: "CAP, AL, 220uF, 25V, +/-20%, 0.15 ohm, SMD"
C4 C5 C6 C7 C8 C18 C19 C20 C21 C22: "CAP, CERM, 100uF, 6.3V, +/-20%, X6S, 1210"
C9 C24: "CAP, CERM, 0.1uF, 25V, +/-10%, X7R, 0805"
C10 C25: "CAP, CERM, 4.7uF, 6.3V, +/-10%, X5R, 0603"
C11 C26: "CAP, CERM, 100pF, 100V, +/-5%, C0G/NP0, 0805"
C12: "CAP, CERM, 3300pF, 50V, +/-10%, X7R, 0805"
C14 C23: "CAP, TA, 220uF, 10V, +/-20%, 0.04 ohm, SMD"
FID1 FID2 FID3: "Fiducial mark.  There is nothing to buy or mount."
H1 H2 H3 H4: "Machine Screw, Round, #4-40 x 1/4, Nylon, Philips panhead"
LBL1: library part THT-14-423-10, "Thermal Transfer Printable Labels, 0.650\" W x 0.200\" H - 10,000 per roll"
Logo1: library part TI_Logo, "Texas Instrument Corporate Signature"
P1 P5: "Header, 100mil, 3x1, Tin plated, TH"
P2 P3: library part HEADER_310-93-102-41, "Header, Female 2-pin, 100mil spacing,"
P4: "Header, 100mil, 4x2, Tin plated, TH"
R1: "RES, 2.15k ohm, 1%, 0.063W, 0402"
R2 R11: "RES, 487k ohm, 1%, 0.063W, 0402"
R3: "RES, 68.1k ohm, 1%, 0.063W, 0402"
R4: "RES, 24.3k ohm, 1%, 0.063W, 0402"
R5: "RES, 1.0k ohm, 5%, 0.125W, 0805"
R6: "RES, 2.87k ohm, 1%, 0.1W, 0603"
R7: "RES, 1.43k ohm, 1%, 0.1W, 0603"
R8: "RES, 715 ohm, 1%, 0.1W, 0603"
R9 R10: "Current Sense Resistor,  SMD, 3W 0.001 ohm, 1%"
R12: "RES, 100k ohm, 5%, 0.1W, 0603"
SH-J1 SH-J2 SH-J3: "Shunt, 2mm, Gold plated, Black"
TB1 TB2 TB3 TB4: "TERMINAL BLOCK 5.08MM VERT 2POS, TH"
TB5: "Terminal Block, 6A, 3.5mm Pitch, 2-Pos, TH"
TP1 TP2: "Test Point, Multipurpose, Red, TH"
TP3 TP4 TP5 TP9: "Test Point, Multipurpose, Black, TH"
TP6 TP7 TP8 TP10 TP11 TP13 TP15 TP16 TP17 TP18: "Test Point, Multipurpose, White, TH"
TP12 TP14: library part TP-038, "Test Point, O.038 Hole"
U1 U2: "10A SIMPLE SWITCHER Power Module with 2.95V-17V Input and Current Sharing in QFN Package, RVQ0042A"
ZZ1 ZZ2 ZZ3: library part AssemblyNote, "This Assembly Note will show in the PcbDoc and associated outputs"

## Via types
v1: diameter 22/22/22/22/22/22 (per signal layer), hole 12, Top Layer to Bottom Layer, 198 vias
v2: diameter 19.68, hole 11.81, Top Layer to Bottom Layer, 28 vias
v3: diameter 50, hole 28, Top Layer to Bottom Layer, 1 vias

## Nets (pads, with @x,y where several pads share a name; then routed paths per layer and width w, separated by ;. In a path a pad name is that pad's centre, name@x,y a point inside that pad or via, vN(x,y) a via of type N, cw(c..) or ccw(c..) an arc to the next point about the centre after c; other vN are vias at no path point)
AGND: C11.2 C12.2 C26.2 P4.1 P4.3 P4.5 P4.7 R1.1 R2.1 R4.1 R11.1 TP3.1 TP4.1 TP5.1 U1.2 U1.23 U1.29 U2.2 U2.23 U2.29 | length 616.4
  Top Layer w10: v1@1410,839.48 U2.2@1441.1,839.48 ; v1@2195,839.48 U1.2@2226.1,839.48 ; U1.23@2613.9,619.01 2654.49,619.01 ; 2692.5,513.5 R2.1@2692.5,551
  MidLayer2 w10: v1(1307.5,838.5) v1(1410,838.5) ; v1(1992.5,761) 2070,838.5 v1(2195,838.5)
  Bottom Layer w10: C26.2@1930,761 v1(1992.5,761) ; C11.2@2768.46,681 v1(2812.5,681) ; C12.2@2780,776 v1(2812.5,776)
CLK_IN: P5.3 R2.2 TP8.1 U1.22 | length 635
  Top Layer w10: U1.22@2613.9,587.52 v1@2647.5,587.52 ; v1(2647.5,588.5) v1@2647.5,587.52 ; R2.2@2692.5,588.5 2692.5,587.52 v1@2647.5,587.52
  MidLayer2 w10: TP8.1@2500,160 2500,222.36 2534,256.36 P5.3@2534,319.5 ; P5.3@2535.5,321 2625,321 2665,361 2665,571 v1(2647.5,588.5)
INH/UVLO: R3.1 R4.2 TP10.1 U1.30 U2.30 | length 2534
  Top Layer w10: U2.30@1828.9,839.48 1860,839.48 1881.52,861 1881.52,927.52 v1(1882.5,928.5) ; U1.30@2613.9,839.48 2645.98,839.48 2657.5,851 2657.5,923.5 v1(2672.5,938.5) R4.2@2751,938.5
  MidLayer2 w10: v1(1882.5,928.5) 2050,1096 2272.5,1096 2365,1003.5 2555,1003.5 2620,938.5 v1(2672.5,938.5) 3590.14,938.5 3787.64,1136 TP10.1@3850,1136
ISHARE: C11.1 C26.1 U1.25 U2.25 | length 1106.8
  Top Layer w10: U2.25@1828.9,682 v1@1859,682 ; U1.25@2613.9,682 2613.9,681 v1(2647.5,681)
  MidLayer2 w10: v1(1862.5,681) 1882.5,681 1912.5,711 2203,711 2349,565 2559,565 2647.5,653.5 v1(2647.5,681)
  Bottom Layer w10: v1(1862.5,681) C26.1@1930,681 ; v1(2647.5,681) C11.1@2700,681
NetP4_2: P4.2 R8.1 | length 77.5
  Bottom Layer w10: R8.1@3027.5,433.5 P4.2@3105,433.5
NetP4_4: P4.4 R7.1 | length 77.5
  Bottom Layer w10: R7.1@3027.5,533.5 P4.4@3105,533.5
NetP4_6: P4.6 R6.1 | length 77.5
  Bottom Layer w10: R6.1@3027.5,633.5 P4.6@3105,633.5
NetP5_2: P5.2 R11.2 U2.22 | length 944.8
  Top Layer w10: U2.22@1828.9,587.52 1885,587.52 ; v1(1885,383.5) 1885,587.52 ; R11.2@1910,586 1908.48,587.52 1885,587.52
  MidLayer2 w10: v1(1885,383.5) 2157.5,383.5 2302.5,241 2415,241 2435,261 P5.2@2435,303.5
NetR9_1: R9.1 TP16.1 | length 112.9
  Bottom Layer w50: TP16.1@2185,1466 2285.9,1466 R9.1@2294.4,1474.5
NetR9_3: R9.3 TP15.1 | length 110.8
  Bottom Layer w50: TP15.1@2185,1181 2290.9,1181 R9.3@2294.4,1177.5
NetR10_1: R10.1 TP18.1 | length 115.4
  Bottom Layer w50: TP18.1@1407.5,1466 1510.9,1466 R10.1@1519.4,1474.5
NetR10_3: R10.3 TP17.1 | length 113.3
  Bottom Layer w50: TP17.1@1407.5,1181 1515.9,1181 R10.3@1519.4,1177.5
NetR12_2: R12.2 TP6.1 | length 134.9
  Bottom Layer w10: TP6.1@981.5,533.5 981.5,468.5 1011.5,438.5 R12.2@1039,438.5
PGND: C1.2 C2.2 C3.2 C4.2 C5.2 C6.2 C7.2 C8.2 C9.2 C10.2 C14.2 C16.2 C17.2 C18.2 C19.2 C20.2 C21.2 C22.2 C23.2 C24.2 C25.2 P2.2 P3.2 R5.2 TB2.1 TB2.2 TB3.1 TB3.2 TB5.1 TP9.1 U1.20 U1.21 U1.31 U1.32 U1.33 U2.20 U2.21 U2.31 U2.32 U2.33 | length 4508.2
  Top Layer w10: U1.33@2514.49,907.4 2514.49,771.51 v1(2517.5,768.5) ; U1.31@2600.12,893.5 U1.31@2600.12,893.62
  MidLayer2 w25: v1@1407.5,1064.5 v1(1407.5,1043.5) v1(1407.5,1021) v1(1407.5,998.5) v1(1407.5,976) v1(1430,976) v1(1430,998.5) v1(1430,1021) v1(1430,1043.5) v1(1430,1066) v1(1407.5,1066) ; v1@1840,1062 v1(1840,1043.5) v1(1840,1021) v1(1840,998.5) v1(1840,976) v1(1862.5,976) v1(1862.5,998.5) v1(1862.5,1021) v1(1862.5,1043.5) v1(1862.5,1066) v1(1840,1066)
  Mid-Layer 3 w23: v1@2517.5,766.5 v1(2517.5,746) v1(2517.5,723.5) v1(2517.5,701) v1(2517.5,678.5) v1(2517.5,656) v1(2517.5,633.5) v1(2540,633.5) v1(2540,656) v1(2540,678.5) v1(2540,701) v1(2540,723.5) v1(2540,746) v1(2540,768.5) v1(2517.5,768.5)
  Mid-Layer 3 w25: v1@1407.5,1064.5 v1(1407.5,1043.5) v1(1407.5,1021) v1(1407.5,998.5) v1(1407.5,976) v1(1430,976) v1(1430,998.5) v1(1430,1021) v1(1430,1043.5) v1(1430,1066) v1(1407.5,1066) ; v1@1732.5,766.5 v1(1732.5,746) v1(1732.5,723.5) v1(1732.5,701) v1(1732.5,678.5) v1(1732.5,656) v1(1732.5,633.5) v1(1755,633.5) v1(1755,656) v1(1755,678.5) v1(1755,701) v1(1755,723.5) v1(1755,746) v1(1755,768.5) v1(1732.5,768.5) ; v1(1765,488.5) v1(1765,466) v1(1787.5,466) v1(1810,466) v1(1832.5,466) v1(1855,466) v1(1855,488.5) v1(1832.5,488.5) v1(1810,488.5) v1(1787.5,488.5) v1@1767.5,488.5 ; v1@1840,1064 v1(1840,1043.5) v1(1840,1021) v1(1840,998.5) v1(1840,976) v1(1862.5,976) v1(1862.5,998.5) v1(1862.5,1021) v1(1862.5,1043.5) v1(1862.5,1066) v1(1840,1066) ; v1@2192.5,1063.5 v1(2192.5,1043.5) v1(2192.5,1021) v1(2192.5,998.5) v1(2192.5,976) v1(2215,976) v1(2215,998.5) v1(2215,1021) v1(2215,1043.5) v1(2215,1066) v1(2192.5,1066) ; v1(2625,1066) v1(2647.5,1066) v1(2647.5,1043.5) v1(2647.5,1021) v1(2647.5,998.5) v1(2647.5,976) v1(2625,976) v1(2625,998.5) v1(2625,1021) v1(2625,1043.5) 2625,1065 v1@2626,1064 ; v1@2637.5,488.5 v1(2617.5,488.5) v1(2595,488.5) v1(2572.5,488.5) v1(2550,488.5) v1(2550,466) v1(2572.5,466) v1(2595,466) v1(2617.5,466) v1(2640,466) v1(2640,488.5)
  Mid-Layer 4 w23: v1(2517.5,633.5) v1(2540,633.5) v1(2540,656) v1(2540,678.5) v1(2540,701) v1(2540,723.5) v1(2540,746) v1(2540,768.5) v1(2517.5,768.5) v1(2517.5,746) v1(2517.5,723.5) v1(2517.5,701) v1(2517.5,678.5) v1(2517.5,656) v1(2517.5,633.5)
  Mid-Layer 4 w25: v1@1407.5,1062.5 v1(1407.5,1043.5) v1(1407.5,1021) v1(1407.5,998.5) v1(1407.5,976) v1(1430,976) v1(1430,998.5) v1(1430,1021) v1(1430,1043.5) v1(1430,1066) v1(1407.5,1066) ; v1@1732.5,767.5 v1(1732.5,746) v1(1732.5,723.5) v1(1732.5,701) v1(1732.5,678.5) v1(1732.5,656) v1(1732.5,633.5) v1(1755,633.5) v1(1755,656) v1(1755,678.5) v1(1755,701) v1(1755,723.5) v1(1755,746) v1(1755,768.5) v1(1732.5,768.5) ; v1@1851.5,488.5 v1(1832.5,488.5) v1(1810,488.5) v1(1787.5,488.5) v1(1765,488.5) v1(1765,466) v1(1787.5,466) v1(1810,466) v1(1832.5,466) v1(1855,466) v1(1855,488.5) ; v1@2192.5,1062.5 v1(2192.5,1043.5) v1(2192.5,1021) v1(2192.5,998.5) v1(2192.5,976) v1(2215,976) v1(2215,998.5) v1(2215,1021) v1(2215,1043.5) v1(2215,1066) v1(2192.5,1066) ; v1@2625,1058 v1(2625,1043.5) v1(2625,1021) v1(2625,998.5) v1(2625,976) v1(2647.5,976) v1(2647.5,998.5) v1(2647.5,1021) v1(2647.5,1043.5) v1(2647.5,1066) v1(2625,1066) ; v1@2637.5,488.5 v1(2617.5,488.5) v1(2595,488.5) v1(2572.5,488.5) v1(2550,488.5) v1(2550,466) v1(2572.5,466) v1(2595,466) v1(2617.5,466) v1(2640,466) v1(2640,488.5) ; v1(1840,976) v1(1862.5,976) v1(1862.5,998.5) v1(1862.5,1021) v1(1862.5,1043.5) v1(1862.5,1066) v1(1840,1066) v1(1840,1043.5) v1(1840,1021) v1(1840,998.5) v1(1840,976)
PH: TP12.1 U1.10 U1.13 U1.14 U1.15 U1.16 U1.17 U1.18 U1.19 U1.42 | length 613.1
  Top Layer w10: TP12.1@2420,435 U1.16@2420,519.6
  MidLayer1 w25: v2(2367.15,613.11) v2(2397.85,613.11) v2(2442.15,613.11) v2(2472.85,613.11)
  MidLayer2 w25: v2(2367.15,613.11) v2(2397.85,613.11) v2(2442.15,613.11) v2(2472.85,613.11)
  Mid-Layer 3 w25: v2(2367.15,613.11) v2(2397.85,613.11) v2(2442.15,613.11) v2(2472.85,613.11)
  Mid-Layer 4 w25: v2(2367.15,613.11) v2(2397.85,613.11) v2(2442.15,613.11) v2(2472.85,613.11)
  Bottom Layer w25: v2(2367.15,613.11) v2(2397.85,613.11) v2(2442.15,613.11) v2(2472.85,613.11)
  other v2: 2397.85,643.82 2442.15,643.82 2397.85,674.52 2442.15,674.52 2397.85,705.23 2442.15,705.23 2397.85,735.94 2442.15,735.94 2397.85,766.65 2442.15,766.65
